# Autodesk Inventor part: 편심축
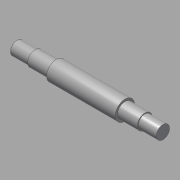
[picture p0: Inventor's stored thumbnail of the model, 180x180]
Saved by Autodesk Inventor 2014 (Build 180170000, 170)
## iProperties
Created: 2015-10
Part Number: 편심축
Document SubType Name: Modeling
Designer: mdu
Density: 7.86 g/cm^3
Material: 강철, 연강
Mass: 1163.82 g
Surface Area: 210.981 cm^2
Volume: 148.069 cm^3
Appearance: 강철
Author: mdu
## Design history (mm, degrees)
sketch "스케치1"
  geometry: L1 (-20.5, -41.331)-(-20.5, 32.669) reference; L2 (7.5, -30.031)-(7.5, 21.369) reference; L3 (135.5, -30.331)-(135.5, 21.669) reference; L4 (121.5, 21.369)-(121.5, -30.031) reference; L5 (184.5, -4.331)-(-7.5, -4.331); L6 (184.5, -4.331)-(184.5, 6.669); L7 (154.5, 8.169)-(121.5, 8.169); L8 (121.5, 8.169)-(121.5, 11.669); L9 (121.5, 11.669)-(7.5, 11.669); L10 (7.5, 11.669)-(7.5, 8.169); L11 (7.5, 8.169)-(-7.5, 8.169); L12 (-7.5, 8.169)-(-7.5, -4.331); L13 (154.5, 8.169)-(154.5, 6.669); L14 (154.5, 6.669)-(184.5, 6.669); C1 r 32.5 at (64.5, -4.331) reference; 1 further point
  constraints: 21 end point, 8 perpendicular, 5 point on line, 1 collinear
  dimensions: "d1" = 25 diameter of L11 L5; "d2" = 32 diameter of L9 L5; "d4" = 15 distance of L10.end L11.end; "d15" = 33 distance of L7.start L7.end; "d26" = 30 distance of L13.end L6.end; "d36" = 22 diameter of L14 L5
revolve "회전1" sketch "스케치1" stored, may be unused: angle "d6" = 90 deg
node "작업 평면1"
sketch "스케치2"
  geometry: C1 r 16 at (0, 0) reference; C2 r 20.75 at (0, 4)
  constraints: 1 centre point, 1 vertical alignment
  dimensions: "d34" = 4 distance of C2.centre C1.centre; "d35" = 41.5 diameter of C2
extrude "돌출1" join sketch "스케치2" stored distance "d9" = 40; taper "d10" = 0 deg
chamfer "모따기1" distance "d11" = 1; stored, may be unused: second distance "d12" = 2, angle "d13" = 45 deg
node "작업 평면2"
sketch "스케치3"
  geometry: L1 (-15, -10)-(-15, 10) reference; L2 (-15, 3)-(0, 3); L3 (0, -3)-(-15, -3); A1 r 3 centre (0, 0) between (0, -3) and (0, 3); 2 further points
  constraints: 4 end point, 2 perpendicular, 2 point on circle, 2 point on line, 2 tangent, 1 centre point, 1 horizontal alignment, 1 midpoint
  dimensions: "d16" = 18 dimension on A1 L1; "d17" = 6 distance between parallel lines of L3 L2
extrude "돌출2" cut sketch "스케치3" distance "d18" = 3.5; taper "d19" = 0 deg
node "솔리드1"
node "참조1"
node "참조2"
node "참조3"
node "참조4"
node "참조5"
other parameters: "d30" = 35
